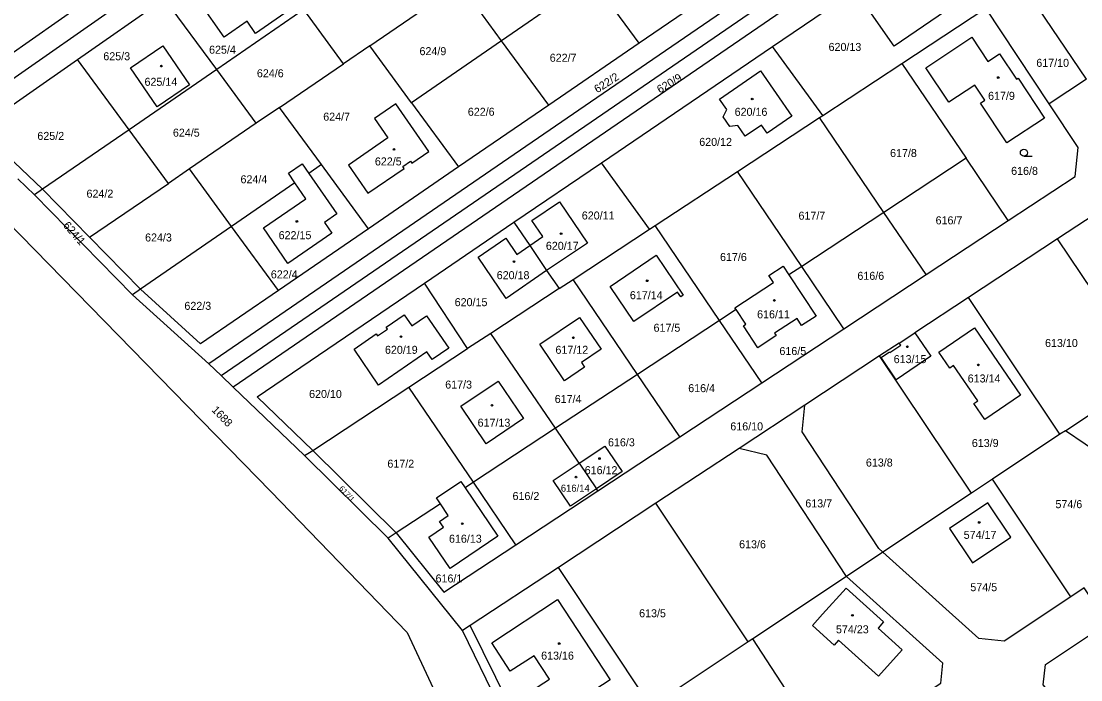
# Model space of a CAD drawing. Extents: x -724107 to -720612, y -1045267 to -1038441.
# Drawn here: x -723206 to -722981, y -1043085.8 to -1042945.9 of the extents above; entities that cross this region are included whole.
import ezdxf

# ---------------------------------------------------------------- set-up
doc = ezdxf.new("R2010")
doc.units = 0
for name, color, linetype in [('Hranice kat_území', 7, 'Continuous'), ('Hranice parcel', 7, 'Continuous'), ('Parcelní čísla', 7, 'Continuous'), ('Značky budov', 7, 'Continuous'), ('Značky kultur', 7, 'Continuous')]:
    doc.layers.add(name, color=color, linetype=linetype)

msp = doc.modelspace()

# ---------------------------------------------------------------- linework, layer by layer
at = {"layer": 'Hranice kat_území'}
msp.add_lwpolyline([(-723212.07, -1042985.4), (-723153.02, -1043045.8), (-723124.07, -1043075.78), (-723072.76, -1043185.61)], dxfattribs=at)
at = {"layer": 'Hranice parcel'}
for p, q in [((-723220.07, -1042966.72), (-723012.48, -1042821.33)), ((-723163.54, -1043021.15), (-723016.22, -1042920.12)), ((-723103.98, -1042950.03), (-723112.8, -1042938.01)), ((-723084.82, -1042936.83), (-723103.98, -1042950.03)), ((-723074.76, -1042950.56), (-723084.82, -1042936.83)), ((-723055.53, -1042937.38), (-723074.76, -1042950.56)), ((-722979.78, -1042958.24), (-722993.36, -1042938.06)), ((-723192.7, -1042942.05), (-723209.08, -1042953.53)), ((-723194.09, -1042954.02), (-723175.57, -1042941.05)), ((-723164.49, -1042956.15), (-723175.57, -1042941.05)), ((-723131.98, -1042951.12), (-723119.2, -1042942.39)), ((-723146, -1042943.43), (-723164.49, -1042956.15)), ((-723137.56, -1042954.93), (-723146, -1042943.43)), ((-723018.97, -1042954.88), (-723001.11, -1042943.15)), ((-722987.67, -1042963.43), (-723001.11, -1042943.15)), ((-723131.98, -1042951.12), (-723137.56, -1042954.93)), ((-723123.12, -1042963.21), (-723131.98, -1042951.12)), ((-723103.98, -1042950.03), (-723123.12, -1042963.21)), ((-723093.94, -1042963.72), (-723103.98, -1042950.03)), ((-723074.76, -1042950.56), (-723093.94, -1042963.72)), ((-723082.79, -1042975.99), (-723046.41, -1042951.26)), ((-723035.77, -1042965.92), (-723046.41, -1042951.26)), ((-723183.12, -1042968.97), (-723194.09, -1042954.02)), ((-723151.14, -1042964.21), (-723137.56, -1042954.93)), ((-723035.77, -1042965.92), (-723018.97, -1042954.88)), ((-723018.97, -1042954.88), (-723005.31, -1042975.03)), ((-723164.49, -1042956.15), (-723183.12, -1042968.97)), ((-723156.09, -1042967.59), (-723164.49, -1042956.15)), ((-722979.78, -1042958.24), (-722987.67, -1042963.43)), ((-723151.14, -1042964.21), (-723156.09, -1042967.59)), ((-723142.24, -1042976.37), (-723151.14, -1042964.21)), ((-723123.12, -1042963.21), (-723113.11, -1042976.87)), ((-723093.94, -1042963.72), (-723113.11, -1042976.87)), ((-723053.91, -1042977.84), (-723036.45, -1042966.36)), ((-723036.45, -1042966.36), (-723035.77, -1042965.92)), ((-723022.78, -1042986.52), (-723036.45, -1042966.36)), ((-723183.12, -1042968.97), (-723201.5, -1042981.61)), ((-723174.77, -1042980.35), (-723183.12, -1042968.97)), ((-723156.09, -1042967.59), (-723170.29, -1042977.29)), ((-723101.36, -1042988.61), (-723082.79, -1042975.99)), ((-723072.56, -1042990.09), (-723082.79, -1042975.99)), ((-723005.31, -1042975.03), (-723022.78, -1042986.52)), ((-722996.35, -1042988.23), (-723005.31, -1042975.03)), ((-723170.29, -1042977.29), (-723174.77, -1042980.35)), ((-723161.33, -1042989.51), (-723170.29, -1042977.29)), ((-723142.24, -1042976.37), (-723144.94, -1042978.23)), ((-723132.26, -1042990), (-723142.24, -1042976.37)), ((-723113.11, -1042976.87), (-723132.26, -1042990)), ((-723071.37, -1042989.3), (-723053.91, -1042977.84)), ((-723040.24, -1042998), (-723053.91, -1042977.84)), ((-723203.17, -1042982.76), (-723206.77, -1042979.37)), ((-723191.53, -1042991.79), (-723174.77, -1042980.35)), ((-723147.88, -1042980.26), (-723161.33, -1042989.51)), ((-722965.86, -1042978.93), (-722985.9, -1042992.13)), ((-723201.5, -1042981.61), (-723203.17, -1042982.76)), ((-723182.4, -1043004.02), (-723203.17, -1042982.76)), ((-723191.53, -1042991.79), (-723201.5, -1042981.61)), ((-723022.78, -1042986.52), (-723040.24, -1042998)), ((-723013.81, -1042999.74), (-723022.78, -1042986.52)), ((-723161.33, -1042989.51), (-723180.71, -1043002.86)), ((-723151.37, -1043003.11), (-723161.33, -1042989.51)), ((-723120.36, -1043001.53), (-723101.36, -1042988.61)), ((-723101.36, -1042988.61), (-723098.01, -1042993.56)), ((-723072.56, -1042990.09), (-723071.37, -1042989.3)), ((-723057.69, -1043009.47), (-723071.37, -1042989.3)), ((-723013.81, -1042999.74), (-722996.35, -1042988.23)), ((-723180.71, -1043002.86), (-723191.53, -1042991.79)), ((-723132.26, -1042990), (-723151.37, -1043003.11)), ((-723088.81, -1043000.76), (-723072.56, -1042990.09)), ((-723098.01, -1042993.56), (-723094.42, -1042998.85)), ((-722985.9, -1042992.13), (-723004.83, -1043004.6)), ((-722966.51, -1043021.13), (-722985.9, -1042992.13)), ((-723040.24, -1042998), (-723042.95, -1042999.78)), ((-723031.26, -1043011.23), (-723040.24, -1042998)), ((-723094.42, -1042998.85), (-723091.79, -1043002.72)), ((-723091.79, -1043002.72), (-723088.81, -1043000.76)), ((-723075.13, -1043020.94), (-723088.81, -1043000.76)), ((-723031.26, -1043011.23), (-723013.81, -1042999.74)), ((-723180.71, -1043002.86), (-723182.4, -1043004.02)), ((-723111.21, -1043015.47), (-723120.36, -1043001.53)), ((-723091.79, -1043002.72), (-723106.26, -1043012.22)), ((-723166.2, -1043018.73), (-723182.4, -1043004.02)), ((-723004.83, -1043004.6), (-723016.23, -1043012.11)), ((-722985.38, -1043033.68), (-723004.83, -1043004.6)), ((-723054.17, -1043007.15), (-723057.69, -1043009.47)), ((-723057.69, -1043009.47), (-723075.13, -1043020.94)), ((-723048.7, -1043022.72), (-723057.69, -1043009.47)), ((-723106.26, -1043012.22), (-723111.21, -1043015.47)), ((-723092.55, -1043032.4), (-723106.26, -1043012.22)), ((-723048.7, -1043022.72), (-723031.26, -1043011.23)), ((-723019.53, -1043014.28), (-723016.23, -1043012.11)), ((-723019.53, -1043014.28), (-723023.69, -1043017.02)), ((-723123.67, -1043023.66), (-723111.21, -1043015.47)), ((-723163.54, -1043021.15), (-723166.2, -1043018.73)), ((-723023.69, -1043017.02), (-723039.56, -1043027.47)), ((-723004.18, -1043046.2), (-723023.69, -1043017.02)), ((-723160.97, -1043023.63), (-723163.54, -1043021.15)), ((-723075.13, -1043020.94), (-723092.55, -1043032.4)), ((-723066.13, -1043034.2), (-723075.13, -1043020.94)), ((-722984.22, -1043032.91), (-722966.51, -1043021.13)), ((-723066.13, -1043034.2), (-723048.7, -1043022.72)), ((-723145.82, -1043038.21), (-723160.97, -1043023.63)), ((-723144.11, -1043037.09), (-723123.67, -1043023.66)), ((-723109.97, -1043043.85), (-723123.67, -1043023.66)), ((-723039.56, -1043027.47), (-723053.54, -1043036.68)), ((-723092.55, -1043032.4), (-723109.97, -1043043.85)), ((-723087.52, -1043039.82), (-723092.55, -1043032.4)), ((-723083.55, -1043045.67), (-723066.13, -1043034.2)), ((-722985.38, -1043033.68), (-722999.71, -1043043.22)), ((-722984.22, -1043032.91), (-722985.38, -1043033.68)), ((-722956.74, -1043051.61), (-722984.22, -1043032.91)), ((-723053.54, -1043036.68), (-723071.2, -1043048.31)), ((-723145.82, -1043038.21), (-723144.11, -1043037.09)), ((-723128.05, -1043055.74), (-723145.82, -1043038.21)), ((-723126.37, -1043054.64), (-723144.11, -1043037.09)), ((-723087.52, -1043039.82), (-723083.83, -1043045.26)), ((-722999.71, -1043043.22), (-723004.18, -1043046.2)), ((-722983.08, -1043068.19), (-722999.71, -1043043.22)), ((-723109.97, -1043043.85), (-723111.74, -1043045.02)), ((-723100.96, -1043057.14), (-723109.97, -1043043.85)), ((-723100.96, -1043057.14), (-723083.55, -1043045.67)), ((-723083.55, -1043045.67), (-723083.83, -1043045.26)), ((-723071.2, -1043048.31), (-723091.93, -1043061.97)), ((-723051.58, -1043077.75), (-723071.2, -1043048.31)), ((-723004.18, -1043046.2), (-723023.01, -1043058.73)), ((-723116.96, -1043048.45), (-723126.37, -1043054.64)), ((-723126.37, -1043054.64), (-723128.05, -1043055.74)), ((-723112.31, -1043075.39), (-723128.05, -1043055.74)), ((-723023.01, -1043058.73), (-723030.75, -1043063.88)), ((-723091.93, -1043061.97), (-723110.63, -1043074.28)), ((-723072.24, -1043091.5), (-723091.93, -1043061.97)), ((-723030.75, -1043063.88), (-723050.65, -1043077.13)), ((-723110.63, -1043074.28), (-723112.31, -1043075.39)), ((-723094.79, -1043106.51), (-723110.63, -1043074.28)), ((-723096.47, -1043107.63), (-723112.31, -1043075.39)), ((-723050.65, -1043077.13), (-723051.58, -1043077.75)), ((-723034.19, -1043102.21), (-723050.65, -1043077.13)), ((-723051.58, -1043077.75), (-723072.24, -1043091.5))]:
    msp.add_line(p, q, dxfattribs=at)
for points in [[(-722977.15, -1042869.19), (-722985.73, -1042894.97), (-723021.14, -1042919.26), (-723083.73, -1042962.18), (-723166.2, -1043018.73)], [(-723016.22, -1042920.12), (-723017.18, -1042925.03), (-723160.97, -1043023.63)], [(-723046.41, -1042951.26), (-723015.08, -1042929.97), (-723009.42, -1042930.61), (-723001.11, -1042943.15)], [(-723162.88, -1042949.27), (-723168.08, -1042941.89), (-723162.92, -1042938.29), (-723162.64, -1042938.69), (-723160.18, -1042936.98), (-723160.47, -1042936.57), (-723157.07, -1042934.19), (-723150.05, -1042944.21), (-723156.23, -1042948.51), (-723158.03, -1042945.88), (-723162.88, -1042949.27)], [(-723012.92, -1042935.72), (-723008.13, -1042942.72), (-723020.61, -1042951.2), (-723025.39, -1042944.31), (-723012.92, -1042935.72)], [(-723000.68, -1042954.45), (-722998.25, -1042952.81), (-722994.64, -1042958.24), (-722994.29, -1042958.02), (-722988.66, -1042966.49), (-722996.66, -1042971.77), (-723002.29, -1042963.29), (-723001.37, -1042962.67), (-723003.49, -1042959.46), (-723009.01, -1042963.13), (-723013.9, -1042955.79), (-723004.07, -1042949.29), (-723000.68, -1042954.45)], [(-723182.83, -1042955.82), (-723175.92, -1042951.11), (-723170.27, -1042959.43), (-723177.16, -1042964.12), (-723182.83, -1042955.82)], [(-723201.5, -1042981.61), (-723215.07, -1042968.71), (-723194.09, -1042954.02)], [(-723057.7, -1042962.46), (-723048.96, -1042956.47), (-723042.37, -1042966.07), (-723047.61, -1042969.69), (-723048.8, -1042967.96), (-723052.24, -1042970.32), (-723053.79, -1042968.09), (-723055.49, -1042968.29), (-723056.94, -1042966.18), (-723056.14, -1042964.67), (-723057.7, -1042962.46)], [(-723124.67, -1042977.16), (-723124.95, -1042976.75), (-723123.34, -1042975.63), (-723123.05, -1042976.03), (-723119.45, -1042973.58), (-723126.42, -1042963.42), (-723130.98, -1042966.54), (-723128.14, -1042970.7), (-723136.53, -1042976.46), (-723132.41, -1042982.46), (-723124.67, -1042977.16)], [(-722996.35, -1042988.23), (-722982.12, -1042978.86), (-722981.49, -1042972.75), (-722987.67, -1042963.43)], [(-723147.88, -1042980.26), (-723149.28, -1042978.21), (-723146.35, -1042976.18), (-723144.94, -1042978.23)], [(-723144.94, -1042978.23), (-723139.01, -1042986.86), (-723141.6, -1042988.67), (-723140.04, -1042990.94), (-723149.39, -1042997.37), (-723154.57, -1042989.82), (-723145.57, -1042983.65), (-723147.88, -1042980.26)], [(-723098.01, -1042993.56), (-723095.25, -1042991.67), (-723097.56, -1042988.26), (-723091.69, -1042984.27), (-723085.72, -1042993.04), (-723094.42, -1042998.85)], [(-723094.42, -1042998.85), (-723102.99, -1043004.8), (-723108.98, -1042996.03), (-723103.11, -1042992.03), (-723100.77, -1042995.44), (-723098.01, -1042993.56)], [(-723075.88, -1043009.74), (-723080.95, -1043002.24), (-723071.12, -1042995.59), (-723065.39, -1043004.1), (-723065.94, -1043004.46), (-723066.61, -1043003.46), (-723075.88, -1043009.74)], [(-723054.17, -1043007.15), (-723054.41, -1043006.78), (-723046.25, -1043001.41), (-723047.22, -1042999.92), (-723044.18, -1042997.92), (-723042.95, -1042999.78)], [(-723042.95, -1042999.78), (-723037.18, -1043008.55), (-723040.26, -1043010.54), (-723041.23, -1043009.05), (-723046.02, -1043012.18), (-723045.68, -1043012.71), (-723049.58, -1043015.27), (-723052.63, -1043010.64), (-723052.11, -1043010.29), (-723054.17, -1043007.15)], [(-723151.37, -1043003.11), (-723167.93, -1043014.46), (-723180.71, -1043002.86)], [(-723144.11, -1043037.09), (-723155.93, -1043025.7), (-723120.36, -1043001.53)], [(-723135.33, -1043015.58), (-723130.62, -1043012.36), (-723130.34, -1043012.77), (-723128.25, -1043011.34), (-723128.53, -1043010.92), (-723124.66, -1043008.27), (-723123.04, -1043010.64), (-723119.9, -1043008.49), (-723115.2, -1043015.34), (-723118.71, -1043017.77), (-723119.86, -1043016.12), (-723130.16, -1043023.23), (-723135.33, -1043015.58)], [(-723086.34, -1043019.42), (-723090.6, -1043022.28), (-723095.86, -1043014.55), (-723087.47, -1043008.86), (-723082.87, -1043015.59), (-723087.02, -1043018.42), (-723086.34, -1043019.42)], [(-723016.23, -1043012.11), (-723012.84, -1043017.04), (-723020.18, -1043022.07), (-723023.37, -1043017.39), (-723021.62, -1043016.18), (-723021.54, -1043016.31), (-723019.21, -1043014.73), (-723019.53, -1043014.28)], [(-723003.54, -1043011.02), (-722993.75, -1043025.35), (-723001.33, -1043030.52), (-723003.67, -1043027.14), (-723002.84, -1043026.57), (-723007.97, -1043019.05), (-723008.81, -1043019.61), (-723011.13, -1043016.21), (-723003.54, -1043011.02)], [(-723104.68, -1043022.4), (-723099.3, -1043030.35), (-723107.25, -1043035.72), (-723112.66, -1043027.73), (-723104.68, -1043022.4)], [(-723023.01, -1043058.73), (-723023.86, -1043057.97), (-723040.12, -1043033.15), (-723039.56, -1043027.47)], [(-723087.52, -1043039.82), (-723082.07, -1043036.19), (-723078.39, -1043041.58), (-723083.83, -1043045.26)], [(-723030.75, -1043063.88), (-723047.64, -1043038.08), (-723053.54, -1043036.68)], [(-723083.83, -1043045.26), (-723089.36, -1043048.94), (-723093.01, -1043043.52), (-723087.52, -1043039.82)], [(-723116.96, -1043048.45), (-723117.81, -1043047.19), (-723112.64, -1043043.69), (-723111.74, -1043045.02)], [(-723111.74, -1043045.02), (-723104.81, -1043055.3), (-723114.92, -1043062.16), (-723119.42, -1043055.52), (-723116.32, -1043053.42), (-723117.15, -1043052.18), (-723115.3, -1043050.91), (-723116.96, -1043048.45)], [(-723000.7, -1043048.22), (-723008.88, -1043053.66), (-723003.99, -1043061.01), (-722995.81, -1043055.56), (-723000.7, -1043048.22)], [(-723126.37, -1043054.64), (-723116.28, -1043067.23), (-723100.96, -1043057.14)], [(-722983.08, -1043068.19), (-722997.21, -1043077.6), (-723002.6, -1043077.08), (-723023.01, -1043058.73)], [(-723034.19, -1043102.21), (-723010.72, -1043086.59), (-723010.24, -1043082.31), (-723030.75, -1043063.88)], [(-722975.28, -1043073.81), (-722980.26, -1043066.32), (-722983.08, -1043068.19)], [(-723024.01, -1043074.87), (-723018.88, -1043079.5), (-723023.95, -1043085.1), (-723032.41, -1043077.43), (-723033.34, -1043078.45), (-723037.95, -1043074.27), (-723035.8, -1043071.88), (-723030.76, -1043066.39), (-723022.87, -1043073.54), (-723024.01, -1043074.87)], [(-723098.86, -1043088.97), (-723093.84, -1043085.7), (-723097.1, -1043080.73), (-723102.13, -1043084), (-723106.07, -1043077.97), (-723092.09, -1043068.81), (-723080.95, -1043085.85), (-723094.93, -1043094.98), (-723098.86, -1043088.97)], [(-722945.06, -1043096.05), (-722960.35, -1043114.76), (-722965.13, -1043114.8), (-722988.93, -1043086.93), (-722988.42, -1043082.56), (-722975.28, -1043073.81)]]:
    msp.add_lwpolyline(points, dxfattribs=at)
at = {"layer": 'Značky budov'}
for centre in [(-723176.25, -1042955.44), (-722998.5, -1042957.87), (-723050.75, -1042962.43), (-723126.85, -1042973.14), (-723147.47, -1042988.44), (-723091.34, -1042991.04), (-723101.36, -1042996.96), (-723073.05, -1043001.05), (-723046.04, -1043005.24), (-723125.36, -1043012.92), (-723088.74, -1043013.16), (-723017.79, -1043015.08), (-723002.71, -1043018.93), (-723106.04, -1043027.51), (-723083.19, -1043038.83), (-723088.18, -1043042.77), (-723112.34, -1043052.67), (-723002.54, -1043052.4), (-723029.46, -1043072.14), (-723091.75, -1043078.13)]:
    msp.add_circle(centre, 0.175, dxfattribs=at)
at = {"layer": 'Značky kultur'}
msp.add_line((-722993.04, -1042974.59), (-722991.29, -1042974.59), dxfattribs=at)
msp.add_circle((-722993.04, -1042973.84), 0.75, dxfattribs=at)

# ---------------------------------------------------------------- texts
at = {"layer": 'Parcelní čísla'}
for s, height, p in [('625/4', 1.7, (-723166.12, -1042952.8)), ('624/9', 1.7, (-723121.42, -1042953.11)), ('620/13', 1.7, (-723034.53, -1042952.21)), ('625/3', 1.7, (-723188.58, -1042954.19)), ('622/7', 1.7, (-723093.76, -1042954.51)), ('624/6', 1.7, (-723155.96, -1042957.81)), ('617/10', 1.7, (-722990.41, -1042955.59)), ('625/14', 1.7, (-723179.83, -1042959.62)), ('617/9', 1.7, (-723000.65, -1042962.6)), ('622/6', 1.7, (-723111.16, -1042965.99)), ('620/16', 1.7, (-723054.48, -1042966)), ('624/7', 1.7, (-723141.87, -1042967.03)), ('625/2', 1.7, (-723202.59, -1042971.12)), ('624/5', 1.7, (-723173.8, -1042970.43)), ('620/12', 1.7, (-723062, -1042972.39)), ('617/8', 1.7, (-723021.47, -1042974.76)), ('622/5', 1.7, (-723130.9, -1042976.54)), ('624/4', 1.7, (-723159.44, -1042980.34)), ('616/8', 1.7, (-722995.75, -1042978.55)), ('624/2', 1.7, (-723192.15, -1042983.39)), ('620/11', 1.7, (-723086.95, -1042988.03)), ('617/7', 1.7, (-723040.92, -1042988.07)), ('616/7', 1.7, (-723011.8, -1042989.06)), ('624/3', 1.7, (-723179.71, -1042992.7)), ('622/15', 1.7, (-723151.34, -1042992.21)), ('620/17', 1.7, (-723094.58, -1042994.47)), ('617/6', 1.7, (-723057.59, -1042996.85)), ('622/4', 1.7, (-723153, -1043000.54)), ('620/18', 1.7, (-723105.02, -1043000.71)), ('616/6', 1.7, (-723028.41, -1043000.85)), ('617/14', 1.7, (-723076.74, -1043004.96)), ('622/3', 1.7, (-723171.36, -1043007.23)), ('620/15', 1.7, (-723113.95, -1043006.45)), ('616/11', 1.7, (-723049.71, -1043009.03)), ('617/5', 1.7, (-723071.71, -1043011.88)), ('613/10', 1.7, (-722988.55, -1043015.13)), ('620/19', 1.7, (-723128.76, -1043016.57)), ('617/12', 1.7, (-723092.54, -1043016.57)), ('616/5', 1.7, (-723044.97, -1043016.83)), ('613/15', 1.7, (-723020.7, -1043018.55)), ('613/14', 1.7, (-723004.98, -1043022.66)), ('617/3', 1.7, (-723115.96, -1043023.96)), ('616/4', 1.7, (-723064.34, -1043024.72)), ('620/10', 1.7, (-723144.87, -1043025.96)), ('617/4', 1.7, (-723092.7, -1043027.02)), ('617/13', 1.7, (-723109.08, -1043032.05)), ('616/10', 1.7, (-723055.4, -1043032.84)), ('616/3', 1.7, (-723081.38, -1043036.23)), ('613/9', 1.7, (-723004.1, -1043036.37)), ('617/2', 1.7, (-723128.24, -1043040.77)), ('613/8', 1.7, (-723026.6, -1043040.53)), ('616/12', 1.7, (-723086.33, -1043042.15)), ('616/2', 1.7, (-723101.66, -1043047.64)), ('616/14', 1.5, (-723091.4, -1043045.87)), ('613/7', 1.7, (-723039.47, -1043049.21)), ('574/6', 1.7, (-722986.34, -1043049.37)), ('616/13', 1.7, (-723115.16, -1043056.71)), ('574/17', 1.7, (-723005.83, -1043055.89)), ('613/6', 1.7, (-723053.53, -1043057.89)), ('616/1', 1.7, (-723118.01, -1043065.16)), ('574/5', 1.7, (-723004.42, -1043067.01)), ('613/5', 1.7, (-723074.77, -1043072.55)), ('574/23', 1.7, (-723032.96, -1043075.96)), ('613/16', 1.7, (-723095.58, -1043081.55))]:
    msp.add_text(s, height=height, dxfattribs=at).set_placement(p)
for s, height, rotation, p in [('622/2', 1.7, 33, (-723083.64, -1042961.24)), ('620/9', 1.7, 31, (-723070.36, -1042961.29)), ('624/1', 1.7, 311, (-723197.23, -1042989.36)), ('1688', 1.7, 314, (-723165.69, -1043028.62)), ('617/1', 1.139, 313, (-723138.59, -1043045.26))]:
    msp.add_text(s, height=height, rotation=rotation, dxfattribs=at).set_placement(p)

doc.saveas('drawing.dxf')
